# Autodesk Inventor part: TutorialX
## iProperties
Created: 2009-05
Part Number: TutorialX
Document SubType Name: Modeling
Designer: Sham
Density: 1 g/cm^3
Author: Sham
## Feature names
1. Extrusion1
2. Fillet2
